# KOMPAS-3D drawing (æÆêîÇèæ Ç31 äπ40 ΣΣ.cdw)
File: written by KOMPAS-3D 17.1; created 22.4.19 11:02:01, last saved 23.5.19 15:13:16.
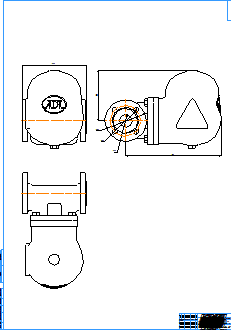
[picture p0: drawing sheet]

Sheet 1: A0, portrait

Title block, sheet 1: name: СТИМАКС А31 Ду40 ф/ф; material: Внимание! Данный продукт является объектом авторского права ООО «Торговый Дом АДЛ». / Запрещается изменение, копирование, распространение / (в том числе путем копирования на другие сайты и ресурсы в Интернете) / или любое иное использование информации и объектов без предварительного / согласия правообладателя (ООО «Торговый Дом АДЛ»).; mass: 35; sheets: 1; organisation: ООО "Торговый дом АДЛ"; sheet format: A0; stored path: \\adlc.lan\data\АДЛ_ПКД\3D-модели\ADL production\Конденсатоотводчики СТИМАКС\Поплавковые\Серия А31\KOMPAS 2D\СТИМАКС А31 Ду40 фф.cdw

Views: Вид 1, Проекционный вид 2, Проекционный вид 3
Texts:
  user
Dimensions and other numbers on the sheet: 230; 343; 181; 46; 150; 110; 1:1; 1; 35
